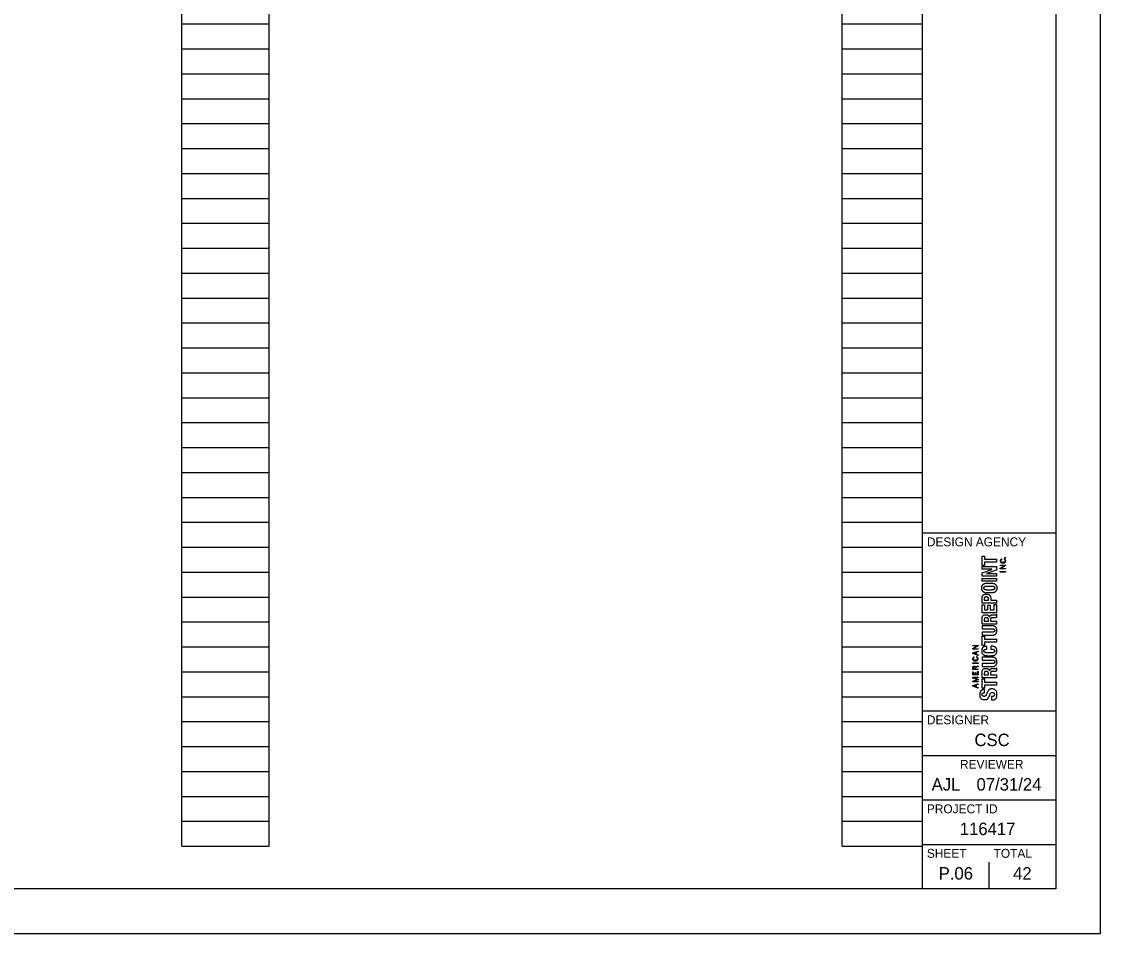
# Model space of a CAD drawing. Extents: x 0 to 83.7, y 0 to 22.
# Drawn here: x 21.88 to 34, y 0 to 10.25 of the extents above; entities that cross this region are included whole.
import ezdxf

# ---------------------------------------------------------------- set-up
doc = ezdxf.new("R2010")
doc.units = 0
for name, color, linetype in [('SH_Border', 7, 'Continuous'), ('SH_Cut_Line', 7, 'Continuous'), ('SH_Data', 7, 'Continuous')]:
    doc.layers.add(name, color=color, linetype=linetype)

msp = doc.modelspace()

# ---------------------------------------------------------------- linework, layer by layer
at = {"layer": 'SH_Border'}
for p, q in [((32, 0.5), (32, 21.5)), ((32, 4.5), (33.5, 4.5)), ((32, 2.5), (33.5, 2.5)), ((32, 2), (33.5, 2)), ((32, 1.5), (33.5, 1.5)), ((32, 1), (33.5, 1))]:
    msp.add_line(p, q, dxfattribs=at)
msp.add_lwpolyline([(1.5, 21.5), (33.5, 21.5), (33.5, 0.5), (1.5, 0.5)], close=True, dxfattribs=at)
at = {"layer": 'SH_Cut_Line'}
msp.add_lwpolyline([(0, 0), (34, 0), (34, 22), (0, 22)], close=True, dxfattribs=at)
at = {"layer": 'SH_Data'}
for p, q in [((23.68, 0.98), (23.68, 21.14)), ((24.66, 0.98), (24.66, 21.14)), ((31.1, 0.98), (31.1, 21.14)), ((32, 0.98), (32, 21.14)), ((23.68, 10.22), (24.66, 10.22)), ((31.1, 10.22), (32, 10.22)), ((23.68, 9.94), (24.66, 9.94)), ((31.1, 9.94), (32, 9.94)), ((23.68, 9.66), (24.66, 9.66)), ((31.1, 9.66), (32, 9.66)), ((23.68, 9.38), (24.66, 9.38)), ((31.1, 9.38), (32, 9.38)), ((23.68, 9.1), (24.66, 9.1)), ((31.1, 9.1), (32, 9.1)), ((23.68, 8.82), (24.66, 8.82)), ((31.1, 8.82), (32, 8.82)), ((23.68, 8.54), (24.66, 8.54)), ((31.1, 8.54), (32, 8.54)), ((23.68, 8.26), (24.66, 8.26)), ((31.1, 8.26), (32, 8.26)), ((23.68, 7.98), (24.66, 7.98)), ((31.1, 7.98), (32, 7.98)), ((23.68, 7.7), (24.66, 7.7)), ((31.1, 7.7), (32, 7.7)), ((23.68, 7.42), (24.66, 7.42)), ((31.1, 7.42), (32, 7.42)), ((23.68, 7.14), (24.66, 7.14)), ((31.1, 7.14), (32, 7.14)), ((23.68, 6.86), (24.66, 6.86)), ((31.1, 6.86), (32, 6.86)), ((23.68, 6.58), (24.66, 6.58)), ((31.1, 6.58), (32, 6.58)), ((23.68, 6.3), (24.66, 6.3)), ((31.1, 6.3), (32, 6.3)), ((23.68, 6.02), (24.66, 6.02)), ((31.1, 6.02), (32, 6.02)), ((23.68, 5.74), (24.66, 5.74)), ((31.1, 5.74), (32, 5.74)), ((23.68, 5.46), (24.66, 5.46)), ((31.1, 5.46), (32, 5.46)), ((23.68, 5.18), (24.66, 5.18)), ((31.1, 5.18), (32, 5.18)), ((23.68, 4.9), (24.66, 4.9)), ((31.1, 4.9), (32, 4.9)), ((23.68, 4.62), (24.66, 4.62)), ((31.1, 4.62), (32, 4.62)), ((23.68, 4.34), (24.66, 4.34)), ((31.1, 4.34), (32, 4.34)), ((23.68, 4.06), (24.66, 4.06)), ((31.1, 4.06), (32, 4.06)), ((23.68, 3.78), (24.66, 3.78)), ((31.1, 3.78), (32, 3.78)), ((23.68, 3.5), (24.66, 3.5)), ((31.1, 3.5), (32, 3.5)), ((32.75, 3.5), (32.75, 3.5)), ((32.75, 3.5), (32.75, 3.5)), ((23.68, 3.22), (24.66, 3.22)), ((31.1, 3.22), (32, 3.22)), ((23.68, 2.94), (24.66, 2.94)), ((31.1, 2.94), (32, 2.94)), ((23.68, 2.66), (24.66, 2.66)), ((31.1, 2.66), (32, 2.66)), ((23.68, 2.38), (24.66, 2.38)), ((31.1, 2.38), (32, 2.38)), ((23.68, 2.1), (24.66, 2.1)), ((31.1, 2.1), (32, 2.1)), ((23.68, 1.82), (24.66, 1.82)), ((31.1, 1.82), (32, 1.82)), ((23.68, 1.54), (24.66, 1.54)), ((31.1, 1.54), (32, 1.54)), ((23.68, 1.26), (24.66, 1.26)), ((31.1, 1.26), (32, 1.26)), ((23.68, 0.98), (24.66, 0.98)), ((31.1, 0.98), (32, 0.98)), ((32.75, 0.5), (32.75, 0.8)), ((32.375, 0.675), (32.375, 0.675))]:
    msp.add_line(p, q, dxfattribs=at)
for points in [[(32.67, 4.239), (32.697, 4.239), (32.697, 4.204), (32.833, 4.204), (32.833, 4.171), (32.697, 4.171), (32.697, 4.135), (32.67, 4.135), (32.67, 4.239)], [(32.67, 4.051), (32.781, 4.091), (32.781, 4.092), (32.67, 4.092), (32.67, 4.122), (32.833, 4.122), (32.833, 4.084), (32.719, 4.044), (32.719, 4.044), (32.833, 4.044), (32.833, 4.013), (32.67, 4.013), (32.67, 4.051)], [(32.875, 4.096), (32.875, 4.105), (32.925, 4.134), (32.925, 4.134), (32.875, 4.134), (32.875, 4.139), (32.935, 4.139), (32.935, 4.134), (32.88, 4.102), (32.88, 4.101), (32.935, 4.101), (32.935, 4.096), (32.875, 4.096)], [(32.935, 4.218), (32.927, 4.218), (32.927, 4.225), (32.935, 4.225), (32.935, 4.218)], [(32.875, 4.061), (32.875, 4.067), (32.935, 4.067), (32.935, 4.061), (32.875, 4.061)], [(32.833, 3.957), (32.67, 3.957), (32.67, 3.99), (32.833, 3.99), (32.833, 3.957)], [(32.833, 3.712), (32.67, 3.712), (32.67, 3.769)], [(32.694, 3.744), (32.743, 3.744), (32.743, 3.759)], [(32.694, 3.758), (32.694, 3.744)], [(32.768, 3.762), (32.768, 3.744), (32.833, 3.744), (32.833, 3.712)], [(32.67, 3.694), (32.697, 3.694), (32.697, 3.635), (32.735, 3.635), (32.735, 3.69), (32.762, 3.69), (32.762, 3.635), (32.806, 3.635), (32.806, 3.696), (32.833, 3.696), (32.833, 3.603), (32.67, 3.603), (32.67, 3.694)], [(32.833, 3.476), (32.67, 3.476), (32.67, 3.537)], [(32.694, 3.525), (32.694, 3.509)], [(32.694, 3.509), (32.741, 3.509), (32.741, 3.523)], [(32.752, 3.554), (32.752, 3.554)], [(32.764, 3.527), (32.764, 3.509), (32.833, 3.509), (32.833, 3.476)], [(32.816, 3.548), (32.784, 3.547)], [(32.832, 3.587), (32.833, 3.587), (32.833, 3.552)], [(32.67, 3.341), (32.697, 3.341), (32.697, 3.305), (32.833, 3.305), (32.833, 3.273), (32.697, 3.273), (32.697, 3.237), (32.67, 3.237), (32.67, 3.341)], [(32.565, 3.194), (32.565, 3.203), (32.615, 3.231), (32.615, 3.231), (32.565, 3.231), (32.565, 3.237), (32.625, 3.237), (32.625, 3.231), (32.569, 3.199), (32.569, 3.199), (32.625, 3.199), (32.625, 3.194), (32.565, 3.194)], [(32.625, 3.125), (32.565, 3.144), (32.565, 3.152), (32.625, 3.171), (32.625, 3.165), (32.605, 3.159), (32.605, 3.137), (32.625, 3.131), (32.625, 3.125)], [(32.601, 3.138), (32.601, 3.158), (32.569, 3.148), (32.569, 3.148), (32.601, 3.138)], [(32.565, 3.034), (32.565, 3.039), (32.625, 3.039), (32.625, 3.034), (32.565, 3.034)], [(32.596, 2.992), (32.625, 3.006), (32.625, 3), (32.597, 2.987), (32.597, 2.971), (32.625, 2.971), (32.625, 2.966), (32.565, 2.966), (32.565, 2.986)], [(32.625, 2.907), (32.565, 2.907), (32.565, 2.941), (32.569, 2.941), (32.569, 2.913), (32.591, 2.913), (32.591, 2.933), (32.596, 2.933), (32.596, 2.913), (32.62, 2.913), (32.62, 2.943), (32.625, 2.943), (32.625, 2.907)], [(32.569, 2.971), (32.593, 2.971), (32.593, 2.986)], [(32.569, 2.986), (32.569, 2.971)], [(32.833, 2.873), (32.67, 2.873), (32.67, 2.934)], [(32.694, 2.922), (32.694, 2.906)], [(32.694, 2.906), (32.741, 2.906), (32.741, 2.92)], [(32.752, 2.951), (32.752, 2.951)], [(32.764, 2.924), (32.764, 2.906), (32.833, 2.906), (32.833, 2.873)], [(32.816, 2.944), (32.784, 2.944)], [(32.832, 2.984), (32.833, 2.984), (32.833, 2.949)], [(32.625, 2.826), (32.565, 2.826), (32.565, 2.836), (32.615, 2.852), (32.615, 2.853), (32.565, 2.869), (32.565, 2.879), (32.625, 2.879), (32.625, 2.873), (32.569, 2.873), (32.569, 2.873), (32.625, 2.855), (32.625, 2.85), (32.569, 2.832), (32.569, 2.832), (32.625, 2.832), (32.625, 2.826)], [(32.625, 2.758), (32.565, 2.777), (32.565, 2.785), (32.625, 2.804), (32.625, 2.798), (32.605, 2.792), (32.605, 2.769), (32.625, 2.763), (32.625, 2.758)], [(32.601, 2.771), (32.601, 2.791), (32.569, 2.781), (32.569, 2.781), (32.601, 2.771)], [(32.67, 2.86), (32.697, 2.86), (32.697, 2.824), (32.833, 2.824), (32.833, 2.791), (32.697, 2.791), (32.697, 2.756), (32.67, 2.756), (32.67, 2.86)]]:
    msp.add_lwpolyline(points, dxfattribs=at)
for points in [[(32.893, 4.201), (32.889, 4.199), (32.885, 4.197), (32.883, 4.195), (32.88, 4.193), (32.879, 4.19), (32.879, 4.186), (32.879, 4.183), (32.88, 4.181), (32.881, 4.178), (32.882, 4.176), (32.884, 4.175), (32.887, 4.173), (32.889, 4.172), (32.892, 4.171), (32.895, 4.17), (32.898, 4.169), (32.902, 4.169), (32.905, 4.169), (32.909, 4.169), (32.912, 4.169), (32.915, 4.17), (32.919, 4.171), (32.921, 4.172), (32.924, 4.173), (32.926, 4.175), (32.928, 4.176), (32.929, 4.179), (32.931, 4.181), (32.931, 4.184), (32.931, 4.187), (32.931, 4.189), (32.931, 4.191), (32.93, 4.193), (32.929, 4.194), (32.928, 4.196), (32.927, 4.197), (32.926, 4.198), (32.924, 4.199), (32.922, 4.2), (32.921, 4.2), (32.919, 4.201), (32.917, 4.202), (32.917, 4.202), (32.918, 4.207), (32.918, 4.207), (32.92, 4.206), (32.923, 4.205), (32.925, 4.204), (32.927, 4.203), (32.929, 4.202), (32.931, 4.2), (32.932, 4.199), (32.934, 4.197), (32.934, 4.195), (32.935, 4.192), (32.936, 4.19), (32.936, 4.187), (32.936, 4.183), (32.935, 4.18), (32.934, 4.177), (32.932, 4.174), (32.93, 4.172), (32.927, 4.17), (32.925, 4.168), (32.921, 4.166), (32.918, 4.165), (32.914, 4.164), (32.91, 4.164), (32.905, 4.164), (32.901, 4.164), (32.896, 4.164), (32.893, 4.165), (32.889, 4.166), (32.886, 4.168), (32.883, 4.17), (32.88, 4.172), (32.878, 4.174), (32.877, 4.177), (32.875, 4.18), (32.875, 4.183), (32.875, 4.187), (32.875, 4.189), (32.875, 4.192), (32.876, 4.194), (32.877, 4.196), (32.878, 4.198), (32.88, 4.199), (32.881, 4.201), (32.883, 4.202), (32.885, 4.203), (32.887, 4.204), (32.889, 4.205), (32.892, 4.206), (32.892, 4.206), (32.893, 4.201), (32.893, 4.201)], [(32.751, 3.826), (32.739, 3.826), (32.727, 3.826), (32.717, 3.828), (32.706, 3.829), (32.697, 3.831), (32.69, 3.835), (32.682, 3.839), (32.677, 3.845), (32.672, 3.852), (32.668, 3.859), (32.666, 3.869), (32.666, 3.882), (32.666, 3.894), (32.668, 3.904), (32.672, 3.911), (32.677, 3.918), (32.682, 3.924), (32.69, 3.928), (32.697, 3.932), (32.706, 3.934), (32.717, 3.936), (32.727, 3.937), (32.739, 3.937), (32.751, 3.937), (32.758, 3.937), (32.764, 3.937), (32.771, 3.937)], [(32.751, 3.859), (32.762, 3.859), (32.771, 3.859), (32.779, 3.859), (32.787, 3.86), (32.793, 3.861), (32.798, 3.863), (32.803, 3.864), (32.806, 3.867), (32.808, 3.87), (32.81, 3.873), (32.812, 3.877), (32.812, 3.882), (32.812, 3.886), (32.81, 3.89), (32.808, 3.893), (32.806, 3.896), (32.803, 3.899), (32.798, 3.9), (32.793, 3.902), (32.787, 3.903), (32.779, 3.904), (32.771, 3.904), (32.762, 3.904), (32.751, 3.904), (32.74, 3.904), (32.731, 3.904), (32.723, 3.904), (32.716, 3.903), (32.709, 3.902), (32.704, 3.9), (32.7, 3.899), (32.696, 3.896), (32.694, 3.893), (32.692, 3.89), (32.691, 3.886), (32.691, 3.882), (32.691, 3.877), (32.692, 3.873), (32.694, 3.87), (32.696, 3.867), (32.7, 3.864), (32.704, 3.863), (32.709, 3.861), (32.716, 3.86), (32.723, 3.859), (32.731, 3.859), (32.74, 3.859), (32.751, 3.859)], [(32.771, 3.937), (32.776, 3.936), (32.781, 3.936), (32.785, 3.936), (32.796, 3.934), (32.805, 3.932), (32.812, 3.928), (32.82, 3.924), (32.825, 3.918), (32.83, 3.911), (32.834, 3.904), (32.836, 3.894), (32.836, 3.882), (32.836, 3.869), (32.834, 3.859), (32.83, 3.852), (32.825, 3.845), (32.82, 3.839), (32.812, 3.835), (32.805, 3.831), (32.796, 3.829), (32.785, 3.828), (32.775, 3.826), (32.763, 3.826), (32.751, 3.826)], [(32.67, 3.769), (32.67, 3.777), (32.671, 3.784), (32.674, 3.79), (32.677, 3.796), (32.68, 3.8), (32.685, 3.804), (32.689, 3.807), (32.695, 3.81), (32.701, 3.812), (32.706, 3.813), (32.712, 3.814), (32.719, 3.814), (32.727, 3.814), (32.734, 3.813), (32.741, 3.81), (32.747, 3.808), (32.752, 3.804), (32.756, 3.8), (32.76, 3.795), (32.763, 3.79), (32.765, 3.783), (32.767, 3.777), (32.768, 3.77), (32.768, 3.762)], [(32.743, 3.759), (32.743, 3.766), (32.741, 3.771), (32.737, 3.775), (32.733, 3.779), (32.727, 3.781), (32.719, 3.781), (32.711, 3.781), (32.705, 3.779), (32.7, 3.776), (32.696, 3.772), (32.694, 3.766), (32.694, 3.758)], [(32.67, 3.537), (32.67, 3.551), (32.673, 3.562), (32.68, 3.569), (32.687, 3.577), (32.698, 3.581), (32.712, 3.581), (32.723, 3.581), (32.732, 3.579), (32.739, 3.574), (32.745, 3.57), (32.75, 3.563), (32.752, 3.554)], [(32.741, 3.523), (32.741, 3.531), (32.739, 3.537), (32.735, 3.542), (32.732, 3.546), (32.725, 3.548), (32.717, 3.548), (32.702, 3.548), (32.694, 3.54), (32.694, 3.525)], [(32.752, 3.554), (32.753, 3.559), (32.755, 3.564), (32.757, 3.567), (32.759, 3.571), (32.762, 3.573), (32.766, 3.575), (32.769, 3.577), (32.774, 3.578), (32.78, 3.579), (32.786, 3.58), (32.794, 3.58), (32.802, 3.58), (32.811, 3.58), (32.818, 3.581), (32.822, 3.582), (32.827, 3.582), (32.83, 3.584), (32.832, 3.587)], [(32.784, 3.547), (32.778, 3.546), (32.773, 3.545), (32.769, 3.542), (32.766, 3.539), (32.764, 3.534), (32.764, 3.527)], [(32.833, 3.552), (32.831, 3.55), (32.828, 3.549), (32.825, 3.549), (32.822, 3.548), (32.819, 3.548), (32.816, 3.548)], [(32.67, 3.385), (32.67, 3.385), (32.783, 3.385), (32.783, 3.385), (32.787, 3.385), (32.791, 3.385), (32.795, 3.386), (32.798, 3.387), (32.801, 3.388), (32.803, 3.389), (32.806, 3.39), (32.808, 3.392), (32.809, 3.395), (32.811, 3.397), (32.812, 3.401), (32.812, 3.404), (32.812, 3.408), (32.811, 3.411), (32.809, 3.414), (32.808, 3.417), (32.806, 3.418), (32.803, 3.42), (32.801, 3.421), (32.798, 3.422), (32.795, 3.423), (32.791, 3.423), (32.787, 3.424), (32.783, 3.424), (32.783, 3.424), (32.67, 3.424), (32.67, 3.424), (32.67, 3.424), (32.67, 3.457), (32.67, 3.457), (32.67, 3.457), (32.783, 3.457), (32.783, 3.457), (32.794, 3.457), (32.802, 3.455), (32.809, 3.452), (32.816, 3.449), (32.821, 3.445), (32.825, 3.441), (32.829, 3.436), (32.832, 3.43), (32.834, 3.424), (32.835, 3.418), (32.836, 3.411), (32.836, 3.404), (32.836, 3.398), (32.835, 3.391), (32.834, 3.385), (32.833, 3.379), (32.83, 3.373), (32.826, 3.368), (32.822, 3.363), (32.817, 3.36), (32.81, 3.357), (32.803, 3.354), (32.794, 3.352), (32.783, 3.352), (32.783, 3.352), (32.67, 3.352), (32.67, 3.352), (32.67, 3.352), (32.67, 3.385), (32.67, 3.385)], [(32.725, 3.193), (32.713, 3.193), (32.704, 3.192), (32.699, 3.189), (32.693, 3.186), (32.691, 3.181), (32.691, 3.174), (32.691, 3.17), (32.692, 3.166), (32.694, 3.163), (32.696, 3.161), (32.7, 3.159), (32.705, 3.157), (32.71, 3.156), (32.716, 3.155), (32.724, 3.154), (32.732, 3.153), (32.742, 3.153), (32.753, 3.153), (32.766, 3.153), (32.776, 3.153), (32.783, 3.154), (32.791, 3.155), (32.797, 3.156), (32.801, 3.158), (32.805, 3.16), (32.808, 3.162), (32.809, 3.165), (32.811, 3.168), (32.812, 3.171), (32.812, 3.174), (32.812, 3.177), (32.811, 3.18), (32.81, 3.182), (32.809, 3.185), (32.807, 3.187), (32.804, 3.189), (32.801, 3.191), (32.797, 3.192), (32.792, 3.193), (32.786, 3.194), (32.779, 3.195), (32.77, 3.195), (32.77, 3.195), (32.77, 3.228), (32.77, 3.228), (32.779, 3.228), (32.787, 3.227), (32.795, 3.226), (32.803, 3.224), (32.81, 3.222), (32.816, 3.218), (32.822, 3.214), (32.827, 3.209), (32.831, 3.202), (32.834, 3.196), (32.836, 3.187), (32.836, 3.176), (32.836, 3.163), (32.834, 3.154), (32.83, 3.146), (32.825, 3.139), (32.82, 3.133), (32.812, 3.129), (32.805, 3.126), (32.796, 3.123), (32.785, 3.122), (32.775, 3.121), (32.763, 3.12), (32.751, 3.12), (32.739, 3.12), (32.727, 3.121), (32.717, 3.122), (32.706, 3.123), (32.697, 3.126), (32.69, 3.129), (32.682, 3.133), (32.677, 3.139), (32.672, 3.146), (32.668, 3.154), (32.666, 3.163), (32.666, 3.176), (32.666, 3.188), (32.668, 3.197), (32.672, 3.204), (32.676, 3.21), (32.681, 3.215), (32.687, 3.219), (32.692, 3.222), (32.699, 3.224), (32.706, 3.225), (32.712, 3.226), (32.719, 3.226), (32.725, 3.226), (32.725, 3.226), (32.725, 3.193), (32.725, 3.193)], [(32.582, 3.101), (32.578, 3.1), (32.575, 3.098), (32.572, 3.095), (32.57, 3.093), (32.569, 3.09), (32.569, 3.086), (32.569, 3.083), (32.569, 3.081), (32.571, 3.079), (32.572, 3.077), (32.574, 3.075), (32.576, 3.074), (32.579, 3.072), (32.581, 3.071), (32.585, 3.07), (32.588, 3.07), (32.591, 3.069), (32.595, 3.069), (32.598, 3.069), (32.602, 3.07), (32.605, 3.07), (32.608, 3.071), (32.611, 3.072), (32.613, 3.074), (32.616, 3.075), (32.618, 3.077), (32.619, 3.079), (32.62, 3.081), (32.621, 3.084), (32.621, 3.087), (32.621, 3.089), (32.62, 3.091), (32.62, 3.093), (32.619, 3.095), (32.618, 3.096), (32.617, 3.097), (32.615, 3.098), (32.614, 3.099), (32.612, 3.1), (32.61, 3.101), (32.608, 3.102), (32.606, 3.102), (32.606, 3.102), (32.607, 3.107), (32.607, 3.107), (32.61, 3.107), (32.612, 3.106), (32.615, 3.105), (32.617, 3.104), (32.619, 3.102), (32.62, 3.101), (32.622, 3.099), (32.623, 3.097), (32.624, 3.095), (32.625, 3.093), (32.625, 3.09), (32.625, 3.087), (32.625, 3.083), (32.625, 3.08), (32.623, 3.077), (32.622, 3.074), (32.62, 3.072), (32.617, 3.07), (32.614, 3.068), (32.611, 3.067), (32.607, 3.066), (32.604, 3.065), (32.599, 3.064), (32.595, 3.064), (32.59, 3.064), (32.586, 3.065), (32.582, 3.066), (32.579, 3.067), (32.575, 3.068), (32.573, 3.07), (32.57, 3.072), (32.568, 3.074), (32.566, 3.077), (32.565, 3.08), (32.564, 3.083), (32.564, 3.087), (32.564, 3.09), (32.565, 3.092), (32.566, 3.094), (32.566, 3.096), (32.568, 3.098), (32.569, 3.099), (32.571, 3.101), (32.572, 3.102), (32.575, 3.103), (32.577, 3.104), (32.579, 3.105), (32.581, 3.106), (32.581, 3.106), (32.582, 3.101), (32.582, 3.101)], [(32.67, 3.032), (32.67, 3.032), (32.783, 3.032), (32.783, 3.032), (32.787, 3.032), (32.791, 3.033), (32.795, 3.033), (32.798, 3.034), (32.801, 3.035), (32.803, 3.036), (32.806, 3.038), (32.808, 3.04), (32.809, 3.042), (32.811, 3.045), (32.812, 3.048), (32.812, 3.052), (32.812, 3.056), (32.811, 3.059), (32.809, 3.061), (32.808, 3.064), (32.806, 3.066), (32.803, 3.067), (32.801, 3.069), (32.798, 3.07), (32.795, 3.07), (32.791, 3.071), (32.787, 3.071), (32.783, 3.071), (32.783, 3.071), (32.67, 3.071), (32.67, 3.071), (32.67, 3.071), (32.67, 3.104), (32.67, 3.104), (32.67, 3.104), (32.783, 3.104), (32.783, 3.104), (32.794, 3.104), (32.802, 3.102), (32.809, 3.1), (32.816, 3.097), (32.821, 3.093), (32.825, 3.088), (32.829, 3.083), (32.832, 3.077), (32.834, 3.071), (32.835, 3.065), (32.836, 3.058), (32.836, 3.052), (32.836, 3.045), (32.835, 3.039), (32.834, 3.032), (32.833, 3.026), (32.83, 3.021), (32.826, 3.016), (32.822, 3.011), (32.817, 3.007), (32.81, 3.004), (32.803, 3.001), (32.794, 3), (32.783, 3), (32.783, 3), (32.67, 3), (32.67, 3), (32.67, 3), (32.67, 3.032), (32.67, 3.032)], [(32.565, 2.986), (32.565, 2.992), (32.566, 2.996), (32.569, 2.999), (32.572, 3.003), (32.576, 3.004), (32.581, 3.004), (32.585, 3.004), (32.588, 3.003), (32.591, 3.001), (32.593, 2.999), (32.595, 2.996), (32.596, 2.992)], [(32.593, 2.986), (32.593, 2.99), (32.592, 2.993), (32.59, 2.995), (32.588, 2.997), (32.585, 2.999), (32.581, 2.999), (32.577, 2.999), (32.575, 2.998), (32.573, 2.995), (32.57, 2.993), (32.569, 2.99), (32.569, 2.986)], [(32.67, 2.934), (32.67, 2.948), (32.673, 2.958), (32.68, 2.966), (32.687, 2.974), (32.698, 2.978), (32.712, 2.978), (32.723, 2.978), (32.732, 2.975), (32.739, 2.971), (32.745, 2.967), (32.75, 2.96), (32.752, 2.951)], [(32.741, 2.92), (32.741, 2.928), (32.739, 2.934), (32.735, 2.938), (32.732, 2.943), (32.725, 2.945), (32.717, 2.945), (32.702, 2.945), (32.694, 2.937), (32.694, 2.922)], [(32.752, 2.951), (32.753, 2.956), (32.755, 2.961), (32.757, 2.964), (32.759, 2.967), (32.762, 2.97), (32.766, 2.972), (32.769, 2.974), (32.774, 2.975), (32.78, 2.976), (32.786, 2.976), (32.794, 2.977), (32.802, 2.977), (32.811, 2.977), (32.818, 2.978), (32.822, 2.978), (32.827, 2.979), (32.83, 2.981), (32.832, 2.984)], [(32.784, 2.944), (32.778, 2.943), (32.773, 2.942), (32.769, 2.939), (32.766, 2.936), (32.764, 2.931), (32.764, 2.924)], [(32.833, 2.949), (32.831, 2.947), (32.828, 2.946), (32.825, 2.945), (32.822, 2.945), (32.819, 2.945), (32.816, 2.944)], [(32.775, 2.661), (32.775, 2.661), (32.781, 2.661), (32.781, 2.661), (32.785, 2.661), (32.789, 2.662), (32.793, 2.662), (32.796, 2.663), (32.799, 2.664), (32.801, 2.666), (32.804, 2.668), (32.806, 2.671), (32.807, 2.674), (32.809, 2.677), (32.809, 2.681), (32.809, 2.686), (32.809, 2.692), (32.807, 2.697), (32.804, 2.701), (32.8, 2.706), (32.794, 2.708), (32.786, 2.708), (32.782, 2.708), (32.779, 2.708), (32.776, 2.707), (32.773, 2.705), (32.77, 2.704), (32.767, 2.701), (32.765, 2.698), (32.763, 2.695), (32.761, 2.691), (32.759, 2.687), (32.757, 2.681), (32.755, 2.675), (32.752, 2.667), (32.749, 2.66), (32.745, 2.654), (32.742, 2.647), (32.738, 2.642), (32.734, 2.638), (32.73, 2.634), (32.725, 2.631), (32.719, 2.629), (32.713, 2.628), (32.706, 2.627), (32.699, 2.627), (32.68, 2.627), (32.667, 2.632), (32.658, 2.642), (32.649, 2.652), (32.644, 2.666), (32.644, 2.684), (32.644, 2.692), (32.645, 2.7), (32.647, 2.707), (32.649, 2.714), (32.651, 2.72), (32.656, 2.725), (32.66, 2.73), (32.665, 2.734), (32.671, 2.737), (32.677, 2.74), (32.685, 2.741), (32.694, 2.741), (32.694, 2.741), (32.699, 2.741), (32.699, 2.741), (32.699, 2.741), (32.699, 2.705), (32.699, 2.705), (32.69, 2.705), (32.683, 2.704), (32.679, 2.701), (32.674, 2.697), (32.671, 2.692), (32.671, 2.685), (32.671, 2.681), (32.672, 2.678), (32.673, 2.675), (32.675, 2.672), (32.676, 2.67), (32.678, 2.668), (32.68, 2.667), (32.682, 2.665), (32.685, 2.665), (32.688, 2.664), (32.69, 2.664), (32.693, 2.664), (32.699, 2.664), (32.704, 2.665), (32.707, 2.668), (32.711, 2.67), (32.715, 2.675), (32.718, 2.683), (32.718, 2.683), (32.731, 2.712), (32.731, 2.712), (32.734, 2.719), (32.737, 2.725), (32.74, 2.729), (32.744, 2.734), (32.747, 2.737), (32.751, 2.74), (32.755, 2.743), (32.76, 2.745), (32.764, 2.746), (32.769, 2.747), (32.774, 2.747), (32.78, 2.747), (32.799, 2.747), (32.814, 2.742), (32.823, 2.73), (32.832, 2.719), (32.837, 2.703), (32.837, 2.683), (32.837, 2.662), (32.832, 2.647), (32.823, 2.638), (32.813, 2.628), (32.8, 2.624), (32.783, 2.624), (32.783, 2.624), (32.775, 2.624), (32.775, 2.624), (32.775, 2.624), (32.775, 2.661), (32.775, 2.661)]]:
    msp.add_open_spline(points, degree=3, dxfattribs=at)

# ---------------------------------------------------------------- texts
for s, height, p in [('DESIGN AGENCY', 0.1, (32.05, 4.35)), ('DESIGNER', 0.1, (32.05, 2.35)), ('CSC', 0.14, (32.585, 2.105)), ('REVIEWER', 0.1, (32.422, 1.85)), ('AJL', 0.14, (32.104, 1.605)), ('07/31/24', 0.14, (32.608, 1.605)), ('PROJECT ID', 0.1, (32.05, 1.35)), ('116417', 0.14, (32.42, 1.105)), ('SHEET', 0.1, (32.05, 0.85)), ('TOTAL', 0.1, (32.8, 0.85)), ('P.06', 0.14, (32.183, 0.605)), ('42', 0.14, (33.019, 0.605))]:
    msp.add_text(s, height=height, dxfattribs=at).set_placement(p)

doc.saveas('drawing.dxf')
